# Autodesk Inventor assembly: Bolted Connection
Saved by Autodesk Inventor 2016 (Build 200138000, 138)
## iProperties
Created: 2016-06
Part Number: Bolted Connection
Document SubType Name: Assembly
Designer: yesi alvarez
ClientObjectVersion: 1
Author: yesi alvarez
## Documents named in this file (1)
- C:\Users\miguel alvarez\Desktop\proyecto del profe. valcarcel\ensamblaje1\Design Accelerator\Bolted Connection3.iam
